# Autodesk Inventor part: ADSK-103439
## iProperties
Shininess: 0.0
Created: 2000-11
Part Number: ADSK-103439
Description: CRS 3/4" THK. x 8" x 10" LONG
Document SubType Name: Modeling
Stock Number: ADSK-103439
Density: 1 g/cm^3
Density: 0.0
Volumn: 0.0
Area: 0.0
PropertySet Name: Model Information
Control State: 0
Master: False
Checked Out: False
Author: gao
